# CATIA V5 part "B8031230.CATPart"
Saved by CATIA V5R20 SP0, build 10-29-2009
Part number: B8031230
Revision: 23
Definition: design
Nomenclature: B8031230
Source: made
Description: NOT SPECIFIED
Bounding box of the stored display mesh (mm): x -12 to 12, y -12 to 12, z 0 to 30
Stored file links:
  C:\Users\Utente\Desktop\3D files B803\B8031230.CATPart
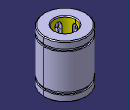
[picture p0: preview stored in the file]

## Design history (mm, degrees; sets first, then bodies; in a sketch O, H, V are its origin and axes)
Body1 "MANIFOLD_SOLID_BREP #38" (main body)
  Solid1: solid without history
Body2 "MANIFOLD_SOLID_BREP #76"
  Solid2: solid without history
Body3 "MANIFOLD_SOLID_BREP #114"
  Solid3: solid without history
Body4 "MANIFOLD_SOLID_BREP #152"
  Solid4: solid without history
Body5 "MANIFOLD_SOLID_BREP #190"
  Solid5: solid without history
Body6 "MANIFOLD_SOLID_BREP #228"
  Solid6: solid without history
Body7 "MANIFOLD_SOLID_BREP #266"
  Solid7: solid without history
Body8 "MANIFOLD_SOLID_BREP #304"
  Solid8: solid without history
Body9 "MANIFOLD_SOLID_BREP #1865"
  Solid9: solid without history
Body10 "MANIFOLD_SOLID_BREP #1903"
  Solid10: solid without history
Body11 "MANIFOLD_SOLID_BREP #1941"
  Solid11: solid without history
Body12 "MANIFOLD_SOLID_BREP #1979"
  Solid12: solid without history
Body13 "MANIFOLD_SOLID_BREP #2017"
  Solid13: solid without history
Body14 "MANIFOLD_SOLID_BREP #2055"
  Solid14: solid without history
Body15 "MANIFOLD_SOLID_BREP #2093"
  Solid15: solid without history
Body16 "MANIFOLD_SOLID_BREP #2131"
  Solid16: solid without history
Body17 "MANIFOLD_SOLID_BREP #2169"
  Solid17: solid without history
Body18 "MANIFOLD_SOLID_BREP #2207"
  Solid18: solid without history
Body19 "MANIFOLD_SOLID_BREP #2245"
  Solid19: solid without history
Body20 "MANIFOLD_SOLID_BREP #2283"
  Solid20: solid without history
Body21 "MANIFOLD_SOLID_BREP #2321"
  Solid21: solid without history
Body22 "MANIFOLD_SOLID_BREP #2359"
  Solid22: solid without history
Body23 "MANIFOLD_SOLID_BREP #2397"
  Solid23: solid without history
Body24 "MANIFOLD_SOLID_BREP #2435"
  Solid24: solid without history
Body25 "MANIFOLD_SOLID_BREP #2473"
  Solid25: solid without history
Body26 "MANIFOLD_SOLID_BREP #2511"
  Solid26: solid without history
Body27 "MANIFOLD_SOLID_BREP #2549"
  Solid27: solid without history
Body28 "MANIFOLD_SOLID_BREP #2587"
  Solid28: solid without history
Body29 "MANIFOLD_SOLID_BREP #2625"
  Solid29: solid without history
Body30 "MANIFOLD_SOLID_BREP #2663"
  Solid30: solid without history
Body31 "MANIFOLD_SOLID_BREP #2701"
  Solid31: solid without history
Body32 "MANIFOLD_SOLID_BREP #2739"
  Solid32: solid without history
Body33 "MANIFOLD_SOLID_BREP #2777"
  Solid33: solid without history
Body34 "MANIFOLD_SOLID_BREP #2815"
  Solid34: solid without history
Body35 "MANIFOLD_SOLID_BREP #2853"
  Solid35: solid without history
Body36 "MANIFOLD_SOLID_BREP #2891"
  Solid36: solid without history
Body37 "MANIFOLD_SOLID_BREP #2929"
  Solid37: solid without history
Body38 "MANIFOLD_SOLID_BREP #2967"
  Solid38: solid without history
Body39 "MANIFOLD_SOLID_BREP #3005"
  Solid39: solid without history
Body40 "MANIFOLD_SOLID_BREP #3043"
  Solid40: solid without history
Body41 "MANIFOLD_SOLID_BREP #3081"
  Solid41: solid without history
